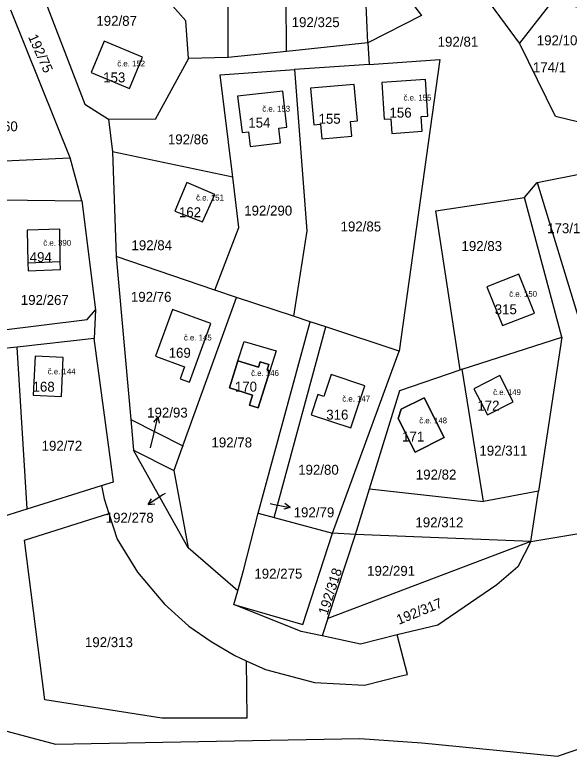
# Model space of a CAD drawing. Extents: x -887272 to -877616, y -1026687 to -1019819.
# Drawn here: x -882394.3 to -882299.4, y -1024320.7 to -1024193.7 of the extents above; entities that cross this region are included whole.
import ezdxf

# ---------------------------------------------------------------- set-up
doc = ezdxf.new("R2010")
doc.units = 0
for name, color, linetype in [('Definiční body', 7, 'Continuous'), ('Hranice parcel', 7, 'Continuous'), ('Parcelní čísla', 7, 'Continuous'), ('Polygon budovy', 7, 'Continuous'), ('Pop  PČ popisy', 7, 'Continuous'), ('Vnitřní kresba', 7, 'Continuous')]:
    doc.layers.add(name, color=color, linetype=linetype)

msp = doc.modelspace()

# ---------------------------------------------------------------- linework, layer by layer
at = {"layer": 'Hranice parcel'}
for p, q in [((-882347.76, -1024199.98), (-882348.11, -1024169.76)), ((-882333.83, -1024198.49), (-882334.7, -1024180.71)), ((-882357.75, -1024201.05), (-882357.82, -1024186.45)), ((-882307.87, -1024198.55), (-882315.45, -1024188.28)), ((-882384.85, -1024218.23), (-882395.01, -1024192.91)), ((-882333.83, -1024198.49), (-882347.76, -1024199.98)), ((-882333.83, -1024198.49), (-882333.65, -1024202.21)), ((-882347.76, -1024199.98), (-882357.75, -1024201.05)), ((-882357.75, -1024201.05), (-882364.57, -1024201.18)), ((-882333.65, -1024202.21), (-882321.52, -1024201.38)), ((-882321.52, -1024201.38), (-882328.48, -1024251.3)), ((-882359.15, -1024203.97), (-882346.41, -1024203.09)), ((-882333.65, -1024202.21), (-882346.41, -1024203.09)), ((-882356.96, -1024221.54), (-882359.15, -1024203.97)), ((-882378.28, -1024211.6), (-882377.61, -1024217.16)), ((-882356.96, -1024221.54), (-882377.61, -1024217.16)), ((-882377.61, -1024217.16), (-882376.96, -1024235.08)), ((-882406.81, -1024219.16), (-882384.85, -1024218.23)), ((-882382.84, -1024225.57), (-882384.85, -1024218.23)), ((-882304.86, -1024222.45), (-882296.53, -1024220.75)), ((-882307, -1024224.99), (-882304.86, -1024222.45)), ((-882396.78, -1024225.38), (-882382.84, -1024225.57)), ((-882382.84, -1024225.57), (-882380.49, -1024244.25)), ((-882300.66, -1024248.91), (-882307, -1024224.99)), ((-882360.05, -1024240.88), (-882376.96, -1024235.08)), ((-882376.96, -1024235.08), (-882374.46, -1024263.02)), ((-882356.35, -1024242.1), (-882360.05, -1024240.88)), ((-882365.56, -1024267.53), (-882356.35, -1024242.1)), ((-882346.59, -1024245.32), (-882356.35, -1024242.1)), ((-882380.49, -1024244.25), (-882380.71, -1024249.15)), ((-882343.72, -1024246.27), (-882346.59, -1024245.32)), ((-882341.03, -1024247.16), (-882343.72, -1024246.27)), ((-882349.89, -1024279.78), (-882341.03, -1024247.16)), ((-882328.48, -1024251.3), (-882341.03, -1024247.16)), ((-882317.71, -1024254.4), (-882300.66, -1024248.91)), ((-882300.66, -1024248.91), (-882304.64, -1024275.27)), ((-882380.71, -1024249.15), (-882393.92, -1024250.6)), ((-882393.92, -1024250.6), (-882404.93, -1024251.81)), ((-882392.22, -1024278.32), (-882393.92, -1024250.6)), ((-882339.9, -1024282.5), (-882328.48, -1024251.3)), ((-882317.71, -1024254.4), (-882318.06, -1024254.51)), ((-882314.06, -1024277.04), (-882317.71, -1024254.4)), ((-882374.46, -1024263.02), (-882365.56, -1024267.53)), ((-882374.46, -1024263.02), (-882373.99, -1024268.29)), ((-882373.99, -1024268.29), (-882367.08, -1024271.72)), ((-882364.65, -1024284.97), (-882373.99, -1024268.29)), ((-882367.08, -1024271.72), (-882364.65, -1024284.97)), ((-882392.22, -1024278.32), (-882379.5, -1024274.33)), ((-882379.5, -1024274.33), (-882379, -1024276.62)), ((-882335.99, -1024282.71), (-882333.57, -1024274.9)), ((-882333.57, -1024274.9), (-882314.06, -1024277.04)), ((-882304.64, -1024275.27), (-882314.06, -1024277.04)), ((-882305.94, -1024283.91), (-882304.64, -1024275.27)), ((-882379, -1024276.62), (-882378.22, -1024279.09)), ((-882401.95, -1024281.38), (-882392.22, -1024278.32)), ((-882352.62, -1024279.03), (-882349.89, -1024279.78)), ((-882349.89, -1024279.78), (-882339.9, -1024282.5)), ((-882305.94, -1024283.91), (-882294.5, -1024282)), ((-882340.7, -1024297.09), (-882335.99, -1024282.71)), ((-882335.99, -1024282.71), (-882339.9, -1024282.5)), ((-882305.94, -1024283.91), (-882335.99, -1024282.71)), ((-882305.94, -1024283.91), (-882340.7, -1024297.09)), ((-882356.14, -1024292.34), (-882364.65, -1024284.97)), ((-882356.8, -1024294.67), (-882356.14, -1024292.34)), ((-882340.7, -1024297.09), (-882341.68, -1024300.07))]:
    msp.add_line(p, q, dxfattribs=at)
for points in [[(-882334.7, -1024180.71), (-882324.68, -1024193.85), (-882333.83, -1024198.49)], [(-882390.17, -1024188.64), (-882382.32, -1024209), (-882378.28, -1024211.6)], [(-882364.57, -1024201.18), (-882365.05, -1024194.74), (-882370.74, -1024188.25)], [(-882287.91, -1024194.55), (-882302.33, -1024191.49), (-882307.87, -1024198.55)], [(-882425.59, -1024292.38), (-882421.44, -1024309.52), (-882387.34, -1024318.62), (-882335.2, -1024317.62), (-882324.6, -1024318.36), (-882301.38, -1024320.66), (-882228.26, -1024295.72), (-882166.04, -1024261.72), (-882132.4, -1024219.02), (-882083.16, -1024195.4)], [(-882372.47, -1024200.97), (-882379.02, -1024198.24), (-882381.26, -1024203.61), (-882374.7, -1024206.34), (-882372.47, -1024200.97)], [(-882293.75, -1024213.08), (-882301.69, -1024211.15), (-882307.87, -1024198.55)], [(-882364.57, -1024201.18), (-882370.29, -1024211.65), (-882378.28, -1024211.6)], [(-882346.41, -1024203.09), (-882344.31, -1024230.73), (-882346.59, -1024245.32)], [(-882341.76, -1024214.98), (-882336.58, -1024214.5), (-882336.82, -1024211.99), (-882335.64, -1024211.88), (-882336.22, -1024205.65), (-882343.69, -1024206.3), (-882343.11, -1024212.57), (-882341.99, -1024212.47), (-882341.76, -1024214.98)], [(-882324.73, -1024211.15), (-882323.57, -1024211.07), (-882324.01, -1024204.8), (-882331.48, -1024205.32), (-882331.04, -1024211.59), (-882329.92, -1024211.51), (-882329.75, -1024214.03), (-882324.56, -1024213.66), (-882324.73, -1024211.15)], [(-882349.12, -1024213.14), (-882347.72, -1024212.98), (-882348.42, -1024206.8), (-882356.2, -1024207.64), (-882355.4, -1024213.88), (-882354.29, -1024213.75), (-882353.99, -1024216.25), (-882348.83, -1024215.65), (-882349.12, -1024213.14)], [(-882360.05, -1024240.88), (-882355.97, -1024230.12), (-882356.96, -1024221.54)], [(-882360.08, -1024224.48), (-882364.86, -1024222.44), (-882366.92, -1024227.36), (-882362.2, -1024229.18), (-882360.08, -1024224.48)], [(-882304.86, -1024222.45), (-882296.39, -1024250.09), (-882285.58, -1024246.47)], [(-882318.06, -1024254.51), (-882322.2, -1024227.27), (-882307, -1024224.99)], [(-882392.06, -1024237.54), (-882386.5, -1024237.34), (-882386.53, -1024235.98), (-882386.63, -1024230.4), (-882392.22, -1024230.57), (-882392.09, -1024236.16), (-882392.06, -1024237.54)], [(-882313.46, -1024240.32), (-882310.8, -1024246.9), (-882305.32, -1024244.78), (-882307.99, -1024238.11), (-882313.46, -1024240.32)], [(-882397.17, -1024247.78), (-882381.94, -1024245.87), (-882380.49, -1024244.25)], [(-882360.75, -1024246.56), (-882367.33, -1024244.15), (-882370.24, -1024252.19), (-882365.28, -1024254.01), (-882366.02, -1024256.06), (-882364.42, -1024256.61), (-882360.75, -1024246.56)], [(-882352.62, -1024279.03), (-882351.55, -1024275.07), (-882343.72, -1024246.27)], [(-882379.5, -1024274.33), (-882377.41, -1024273.67), (-882380.71, -1024249.15)], [(-882354.14, -1024260.55), (-882353.6, -1024258.83), (-882357.56, -1024257.58), (-882356.1, -1024252.96), (-882355.05, -1024249.64), (-882349.56, -1024251.25), (-882350.64, -1024254.68), (-882352.64, -1024261.02), (-882354.14, -1024260.55)], [(-882391.15, -1024258.82), (-882386.34, -1024259.06), (-882386.01, -1024252.42), (-882390.82, -1024252.18), (-882391.15, -1024258.82)], [(-882336.79, -1024264.46), (-882334.39, -1024257.24), (-882340.13, -1024255.33), (-882341.38, -1024259.08), (-882342.43, -1024258.74), (-882343.58, -1024262.2), (-882336.79, -1024264.46)], [(-882333.57, -1024274.9), (-882328.36, -1024258.07), (-882318.06, -1024254.51)], [(-882308.98, -1024260.01), (-882311.25, -1024255.5), (-882315.71, -1024257.75), (-882313.39, -1024262.23), (-882308.98, -1024260.01)], [(-882320.76, -1024266.08), (-882325.76, -1024268.62), (-882328.68, -1024262.86), (-882328.13, -1024261.26), (-882324.19, -1024259.33), (-882320.76, -1024266.08)], [(-882365.56, -1024267.53), (-882365.7, -1024267.92), (-882367.08, -1024271.72)], [(-882354.68, -1024304.32), (-882354.6, -1024314.14), (-882369.14, -1024314.18), (-882389.2, -1024310.99), (-882392.65, -1024283.66), (-882378.22, -1024279.09)], [(-882378.22, -1024279.09), (-882376.81, -1024283.53), (-882373.32, -1024289.17), (-882368.7, -1024294.66), (-882364.52, -1024298.39), (-882360.7, -1024301.04), (-882356.66, -1024303.42), (-882354.68, -1024304.32)], [(-882356.14, -1024292.34), (-882355.16, -1024288.88), (-882352.62, -1024279.03)], [(-882356.8, -1024294.67), (-882344.99, -1024298.1), (-882339.9, -1024282.5)], [(-882305.94, -1024283.91), (-882308.16, -1024288.24), (-882311.77, -1024291.31), (-882321.85, -1024298.23), (-882328.81, -1024299.87)], [(-882341.68, -1024300.07), (-882345.28, -1024299.31), (-882356.8, -1024294.67)], [(-882354.68, -1024304.32), (-882351.37, -1024305.83), (-882343, -1024308.06), (-882334.42, -1024308.5), (-882328.14, -1024306.91), (-882327.09, -1024306.65), (-882328.81, -1024299.87)], [(-882328.81, -1024299.87), (-882335.11, -1024301.46), (-882341.68, -1024300.07)]]:
    msp.add_lwpolyline(points, dxfattribs=at)
at = {"layer": 'Polygon budovy'}
for points in [[(-882379.02, -1024198.24), (-882381.26, -1024203.61), (-882374.7, -1024206.34), (-882372.47, -1024200.97)], [(-882331.04, -1024211.59), (-882329.92, -1024211.51), (-882329.75, -1024214.03), (-882324.56, -1024213.66), (-882324.73, -1024211.15), (-882323.57, -1024211.07), (-882324.01, -1024204.8), (-882331.48, -1024205.32)], [(-882356.2, -1024207.64), (-882355.4, -1024213.88), (-882354.29, -1024213.75), (-882353.99, -1024216.25), (-882348.83, -1024215.65), (-882349.12, -1024213.14), (-882347.72, -1024212.98), (-882348.42, -1024206.8)], [(-882364.86, -1024222.44), (-882366.92, -1024227.36), (-882362.2, -1024229.18), (-882360.08, -1024224.48)], [(-882392.22, -1024230.57), (-882392.09, -1024236.16), (-882386.53, -1024235.98), (-882386.63, -1024230.4)], [(-882305.32, -1024244.78), (-882307.99, -1024238.11), (-882313.46, -1024240.32), (-882310.8, -1024246.9)], [(-882367.33, -1024244.15), (-882370.24, -1024252.19), (-882365.28, -1024254.01), (-882366.02, -1024256.06), (-882364.42, -1024256.61), (-882360.75, -1024246.56)], [(-882386.01, -1024252.42), (-882390.82, -1024252.18), (-882391.15, -1024258.82), (-882386.34, -1024259.06)], [(-882356.1, -1024252.96), (-882357.56, -1024257.58), (-882353.6, -1024258.83), (-882354.14, -1024260.55), (-882352.64, -1024261.02), (-882350.64, -1024254.68), (-882351.12, -1024254.53), (-882350.83, -1024253.6), (-882352.28, -1024253.15), (-882352.57, -1024254.07)], [(-882340.13, -1024255.33), (-882341.38, -1024259.08), (-882342.43, -1024258.74), (-882343.58, -1024262.2), (-882336.79, -1024264.46), (-882334.39, -1024257.24)], [(-882313.39, -1024262.23), (-882308.98, -1024260.01), (-882311.25, -1024255.5), (-882315.71, -1024257.75)], [(-882324.19, -1024259.33), (-882328.13, -1024261.26), (-882328.68, -1024262.86), (-882325.76, -1024268.62), (-882320.76, -1024266.08)]]:
    msp.add_lwpolyline(points, close=True, dxfattribs=at)
at = {"layer": 'Pop  PČ popisy'}
for p, q in [((-882369.85, -1024262.58), (-882370.57, -1024263.44)), ((-882370.53, -1024265.5), (-882369.85, -1024262.58)), ((-882369.85, -1024262.58), (-882369.59, -1024263.66)), ((-882371.09, -1024267.88), (-882370.53, -1024265.5)), ((-882368.56, -1024275.67), (-882368.94, -1024275.92)), ((-882368.94, -1024275.92), (-882371.46, -1024277.55)), ((-882371.46, -1024277.55), (-882370.89, -1024276.59)), ((-882371.46, -1024277.55), (-882370.34, -1024277.43)), ((-882350.56, -1024277.42), (-882350.12, -1024277.51)), ((-882350.12, -1024277.51), (-882347.17, -1024278.08)), ((-882347.17, -1024278.08), (-882348.25, -1024278.38)), ((-882347.17, -1024278.08), (-882348.06, -1024277.4))]:
    msp.add_line(p, q, dxfattribs=at)
at = {"layer": 'Vnitřní kresba'}
for p, q in [((-882392.09, -1024236.16), (-882386.53, -1024235.98)), ((-882356.1, -1024252.96), (-882352.57, -1024254.07)), ((-882352.57, -1024254.07), (-882352.28, -1024253.15)), ((-882352.28, -1024253.15), (-882350.83, -1024253.6)), ((-882350.83, -1024253.6), (-882351.12, -1024254.53)), ((-882351.12, -1024254.53), (-882350.64, -1024254.68))]:
    msp.add_line(p, q, dxfattribs=at)

# ---------------------------------------------------------------- texts
at = {"layer": 'Definiční body'}
for s, p in [('č.e. 152', (-882376.77, -1024202.56)), ('č.e. 155', (-882327.74, -1024208.4)), ('č.e. 153', (-882351.93, -1024210.3)), ('č.e. 151', (-882363.27, -1024225.52)), ('č.e. 390', (-882389.44, -1024233.26)), ('č.e. 150', (-882309.64, -1024242)), ('č.e. 145', (-882365.36, -1024249.48)), ('č.e. 144', (-882388.68, -1024255.28)), ('č.e. 146', (-882353.85, -1024255.56)), ('č.e. 149', (-882312.4, -1024258.83)), ('č.e. 147', (-882338.23, -1024259.95)), ('č.e. 148', (-882325.05, -1024263.67))]:
    msp.add_text(s, height=1, dxfattribs=at).set_placement(p)
at = {"layer": 'Parcelní čísla'}
for s, p in [('192/87', (-882380.35, -1024195.6)), ('192/325', (-882346.9, -1024195.83)), ('192/81', (-882321.9, -1024199.17)), ('192/109', (-882304.92, -1024198.93)), ('174/1', (-882305.59, -1024203.56)), ('153', (-882379.18, -1024205.29)), ('156', (-882330.15, -1024211.32)), ('155', (-882342.3, -1024212.37)), ('192/60', (-882400.77, -1024213.66)), ('154', (-882354.33, -1024213.03)), ('192/86', (-882368.1, -1024215.89)), ('162', (-882366.21, -1024228.37)), ('192/290', (-882355.03, -1024228.09)), ('192/85', (-882338.53, -1024230.81)), ('173/1', (-882303.15, -1024231.11)), ('192/84', (-882374.34, -1024234.02)), ('192/83', (-882317.82, -1024234.16)), ('494', (-882391.77, -1024236.06)), ('192/76', (-882374.44, -1024242.86)), ('192/267', (-882393.29, -1024243.39)), ('315', (-882312.13, -1024245)), ('169', (-882367.97, -1024252.44)), ('168', (-882391.28, -1024258.25)), ('170', (-882356.63, -1024258.24)), ('172', (-882315.1, -1024261.49)), ('192/93', (-882371.66, -1024262.68)), ('316', (-882340.98, -1024263.03)), ('171', (-882327.99, -1024266.78)), ('192/72', (-882389.73, -1024268.36)), ('192/78', (-882360.64, -1024267.79)), ('192/311', (-882314.75, -1024269.19)), ('192/80', (-882345.79, -1024272.47)), ('192/82', (-882325.64, -1024273.29)), ('192/79', (-882346.56, -1024279.76)), ('192/278', (-882378.75, -1024280.68)), ('192/312', (-882325.71, -1024281.48)), ('192/291', (-882333.98, -1024289.78)), ('192/275', (-882353.29, -1024290.26)), ('192/313', (-882382.31, -1024301.99))]:
    msp.add_text(s, height=1.7, dxfattribs=at).set_placement(p)
for s, rotation, p in [('192/75', 294, (-882392.09, -1024197.49)), ('192/318', 72, (-882340.78, -1024296.61)), ('192/317', 22, (-882328.54, -1024298.17))]:
    msp.add_text(s, height=1.7, rotation=rotation, dxfattribs=at).set_placement(p)

doc.saveas('drawing.dxf')
